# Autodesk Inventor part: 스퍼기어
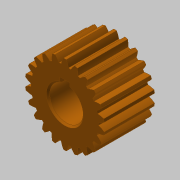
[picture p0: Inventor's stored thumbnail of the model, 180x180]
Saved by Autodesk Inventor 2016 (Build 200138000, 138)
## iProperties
Created: 2019-03
Part Number: 스퍼기어
Material: 강철
Document SubType Name: Modeling
Designer: mduedu
Categories: <?xml version="1.0" encoding="UTF-16"?> <MemberInstance><Categories><FamilyTemplate><FamilyTemplateParameter ValueType="xs:double" Id="1" ObjectReferenceKey="da
Density: 1 g/cm^3
Appearance: 주황색
CustomPartVersion: 1
Author: mduedu
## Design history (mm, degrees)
sketch "Sketch1"
  geometry: C1 r 23.6 at (0, 0)
  constraints: 1 centre point
  dimensions: "d0" = 47.2 diameter of C1 (= da_da)
extrude "Extrusion1" new body sketch "Sketch1" distance "d1" = 30 (= da_b); taper "d2" = 0 deg
workplane "Work Plane2"
sketch "Sketch2"
  geometry: C1 r 23.6 at (0, 0) reference; C2 r 22 at (0, 0)
  constraints: 1 centre point, 1 coincident
  dimensions: "d3" = 44 diameter of C2 (= da_dw)
feature "피치 지름" sketch "Sketch2" dims "d4" = 10, "d5" = 0
workplane "Work Plane8"
workplane "Work Plane9"
feature "스퍼 기어" dims "d3" = 44 (= da_dw), "da_b" = 30, "da_d" = 44, "da_aw" = 44, "da_da" = 47.2, "da_df" = 40.172, "da_dw" = 44, angle "da_beta" = 0 deg, "da_lefttooth" = 0, "da_righttooth" = 0
sketch "스케치3"
  geometry: L1 (-3, 9.539)-(3, 9.539); L2 (3, 9.539)-(3, 12.8); L3 (3, 12.8)-(-3, 12.8); L4 (-3, 12.8)-(-3, 9.539); A1 r 10 centre (0, 0) between (-3, 9.539) and (3, 9.539); 1 further point
  constraints: 8 end point, 2 parallel, 2 point on circle, 1 centre point, 1 coincident, 1 horizontal, 1 perpendicular
  dimensions: "d49" = 20 diameter of A1; "d50" = 6 distance of L2.end L3.end; "d51" = 22.8 dimension on A1 L3
extrude "돌출2" cut sketch "스케치3" stored distance "d52" = 10; taper "d53" = 0 deg
chamfer "모따기1" distance "d54" = 1; stored, may be unused: second distance "d55" = 2, angle "d56" = 45 deg
body "Solid1"
body "Srf1"
other parameters: "d16" = 44 (= da_aw), "d17" = 0, "d34" = 1.428 (computed from da_z), "d39" = 0, "d41" = 0, "d43" = 44 (= da_aw), "d46" = 44 (= da_aw), "d47" = 0, "d48" = 0
